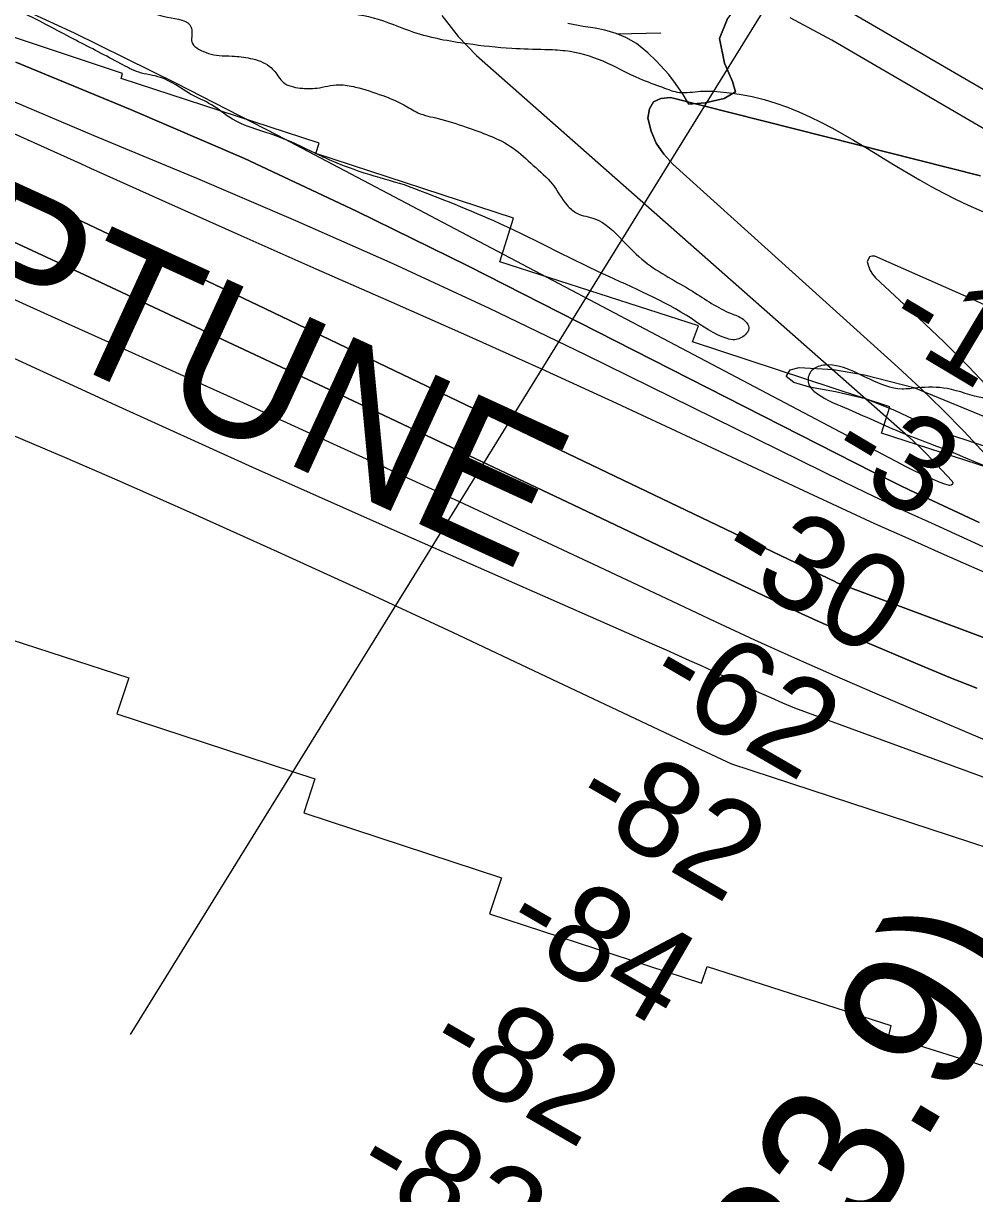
# Model space of a CAD drawing. Extents: x 3855477 to 3893699, y 299188 to 325115.
# Drawn here: x 3860894 to 3861561, y 316616 to 317436 of the extents above; entities that cross this region are included whole.
import ezdxf

# ---------------------------------------------------------------- set-up
doc = ezdxf.new("R2010")
doc.units = 0
for name, color, linetype in [('V-CHAN-NAID', 7, 'Continuous'), ('V-RIVR-EDGE', 7, 'Continuous'), ('V-RIVR-RANG', 7, 'Continuous'), ('V-RRAP-RVMT', 7, 'Continuous'), ('V-RRAP-RVMT-IDEN', 7, 'Continuous'), ('V-TOPO-DPTH', 7, 'Continuous'), ('V-TOPO-MAJR', 7, 'Continuous'), ('V-TOPO-MINR', 7, 'Continuous'), ('V-TOPO-SHOR', 7, 'Continuous'), ('V-TOPO-WATR', 7, 'Continuous'), ('V-WETL-SWMP', 7, 'Continuous')]:
    doc.layers.add(name, color=color, linetype=linetype)

msp = doc.modelspace()

# ---------------------------------------------------------------- linework, layer by layer
at = {"layer": 'V-RIVR-EDGE'}
for points in [[(3859519.27, 318133.34), (3859529.08, 318128.12), (3859557.75, 318117.29), (3859589.18, 318096.89), (3859608.3, 318091.66), (3859632.6, 318087.21), (3859655.71, 318083.17), (3859677.62, 318079.13), (3859695.14, 318076.3), (3859736.57, 318066.23), (3859764.45, 318061.38), (3859790.33, 318051.75), (3859824.18, 318038.52), (3859868.37, 318020.07), (3859890.67, 318012.05), (3859919.33, 318000.82), (3859946.39, 317985.21), (3859972.27, 317972.39), (3859987.4, 317965.98), (3859998.95, 317963.16), (3860007.3, 317958.36), (3860026.81, 317947.55), (3860045.91, 317937.54), (3860071.38, 317923.92), (3860094.87, 317913.9), (3860108.41, 317909.49), (3860130.3, 317897.08), (3860149.8, 317885.47), (3860170.5, 317876.25), (3860195.19, 317867.82), (3860221.06, 317854.21), (3860250.51, 317837.4), (3860275.18, 317822.59), (3860303.05, 317809.37), (3860359.56, 317779.34), (3860406.54, 317758.5), (3860436.79, 317744.08), (3860477.8, 317728.83), (3860496.52, 317723.61), (3860519.21, 317713.19), (3860555.84, 317695.96), (3860594.84, 317675.54), (3860632.26, 317656.32), (3860676.44, 317633.09), (3860726.58, 317605.47), (3860767.97, 317581.06), (3860790.66, 317570.64), (3860877.81, 317518.61), (3860907.67, 317504.59), (3860923.6, 317499.77), (3860947.49, 317491.74), (3860980.94, 317479.3), (3861011.2, 317471.26), (3861035.1, 317464.42), (3861065.37, 317455.98), (3861094.05, 317449.13), (3861112.77, 317445.1), (3861139.06, 317440.25), (3861167.33, 317430.22), (3861205.17, 317422.16), (3861236.25, 317418.89), (3861259.36, 317418.04), (3861273.71, 317417.2), (3861299.99, 317409.96), (3861325.86, 317397.55), (3861341.79, 317391.53), (3861353.74, 317387.91), (3861368.49, 317388.67), (3861377.65, 317388.65), (3861664.73, 317282.73), (3861681.06, 317276.71), (3861681.05, 317274.32), (3861687.02, 317270.72), (3861700.16, 317265.1), (3861705.72, 317256.72), (3861715.66, 317246.33), (3861721.22, 317241.54), (3861723.2, 317234.36), (3861726.37, 317227.58), (3861750.63, 317207.99), (3861757.38, 317197.61), (3861762.54, 317188.83), (3861767.32, 317187.22), (3861780.07, 317185.6), (3861788.02, 317178.01), (3861803.13, 317165.22), (3861810.27, 317151.65), (3861809.85, 317139.69), (3861814.21, 317132.91), (3861819.77, 317124.13), (3861817.34, 317108.59), (3861814.52, 317094.25), (3861799.35, 317086.71), (3861786.59, 317080.77), (3861777.01, 317076.81), (3861766.22, 317064.08), (3861761.83, 317062.89), (3861758.65, 317067.29), (3861753.91, 317083.24), (3861749.94, 317087.23), (3861742.77, 317089.64), (3861728.42, 317090.08), (3861720.06, 317091.29), (3861710.51, 317097.3), (3861701.37, 317107.68), (3861698.2, 317118.05), (3861695.03, 317124.04), (3861685.48, 317130.44), (3861670.34, 317131.27), (3861652.81, 317132.51), (3861648.43, 317134.11), (3861621.76, 317148.93), (3861610.22, 317154.53), (3861601.85, 317155.35), (3861592.29, 317158.16), (3861585.13, 317163.76), (3861576.78, 317170.96), (3861567.22, 317173.37), (3861541.33, 317180.21), (3861520.61, 317180.66), (3861509.85, 317179.89), (3861487.15, 317186.72), (3861457.28, 317196.76), (3861452.1, 317195.97), (3861445.31, 317191.21), (3861444.5, 317182.84), (3861448.07, 317178.45), (3861469.56, 317166.84), (3861510.97, 317148.8), (3861530.48, 317141.18), (3861552.77, 317132.36), (3861596.96, 317112.72)], [(3861161.09, 317323.03), (3861105.34, 317341.9), (3861095.39, 317346.7), (3861067.12, 317358.73), (3861040.44, 317369.16), (3861025.72, 317379.16), (3861011, 317386.77), (3860989.9, 317398.38), (3860974.77, 317402), (3860962.03, 317408.01), (3860930.58, 317424.43), (3860862.12, 317458.07), (3860828.68, 317471.31), (3860810.36, 317480.12), (3860790.46, 317487.34), (3860766.97, 317499.76), (3860758.62, 317504.56), (3860752.25, 317510.16), (3860744.29, 317512.57), (3860727.96, 317516.19), (3860714.02, 317522.6), (3860687.35, 317534.23), (3860666.25, 317542.25), (3860648.74, 317551.46), (3860633.21, 317559.47), (3860610.51, 317563.91), (3860578.66, 317578.73), (3860544.85, 317603.13), (3860519.78, 317618.33), (3860492.31, 317632.35), (3860481.57, 317638.75), (3860472.42, 317647.15), (3860466.06, 317652.34), (3860459.29, 317656.74), (3860442.18, 317667.15), (3860421.09, 317679.16), (3860388.85, 317695.18), (3860368.15, 317703.6), (3860300.85, 317726.08), (3860260.24, 317741.33), (3860222.81, 317756.17), (3860187.38, 317771.8), (3860146.39, 317795.01), (3860128.08, 317804.22), (3860109.37, 317812.24), (3860044.46, 317834.72), (3859988.33, 317859.57), (3859925.43, 317886.82), (3859887.6, 317901.26), (3859853.75, 317911.71), (3859831.85, 317919.73), (3859802.79, 317932.96), (3859772.93, 317945.78), (3859734.71, 317960.23), (3859695.31, 317982.64), (3859660.3, 318005.45), (3859631.23, 318017.47), (3859592.21, 318031.92), (3859552, 318047.96), (3859520.42, 318061.02)], [(3859768.39, 318041.05), (3859805.82, 318029), (3859833.68, 318015.78), (3859870.71, 318001.74), (3859904.56, 317989.3), (3859933.62, 317976.07), (3859963.48, 317964.04), (3859984.98, 317954.03), (3860008.45, 317939.62), (3860049.45, 317917.2), (3860076.91, 317902.79), (3860098.01, 317895.16), (3860117.92, 317885.15), (3860137.81, 317872.35), (3860159.31, 317862.33), (3860181.6, 317854.31), (3860199.92, 317845.89), (3860220.61, 317833.09), (3860254.84, 317816.26), (3860275.54, 317805.45), (3860323.69, 317776.64), (3860351.16, 317763.42), (3860381.01, 317748.6), (3860409.28, 317737.77), (3860435.16, 317727.74), (3860478.16, 317711.3), (3860508.02, 317698.07), (3860533.49, 317684.46), (3860610.33, 317651.59), (3860643.76, 317633.17), (3860673.2, 317613.57), (3860699.46, 317595.17), (3860724.93, 317580.37), (3860751.2, 317565.95), (3860789.01, 317546.33), (3860819.26, 317530.71), (3860850.69, 317509.91), (3860873.37, 317496.31), (3860894.85, 317480.31), (3860901.61, 317471.53), (3860901.6, 317468.74), (3860907.58, 317469.12), (3860918.73, 317465.11), (3860923.51, 317464.7), (3860931.48, 317464.68), (3860947.81, 317458.66), (3860971.69, 317449.04), (3860994.79, 317440.61), (3861011.51, 317433.39), (3861011.9, 317431.8), (3861012.28, 317422.23), (3861016.65, 317418.24), (3861030.99, 317413.82), (3861040.15, 317413.4), (3861052.9, 317411.77), (3861066.44, 317406.16), (3861070.02, 317402.56), (3861075.98, 317394.98), (3861087.92, 317390.96), (3861099.48, 317390.93), (3861115.03, 317393.28), (3861126.58, 317391.66), (3861145.7, 317385.64), (3861160.43, 317379.22), (3861170.38, 317373.62), (3861184.71, 317369.6), (3861204.23, 317363.57), (3861220.55, 317357.55), (3861237.27, 317348.75), (3861251.19, 317336.75), (3861264.71, 317323.57), (3861275.03, 317308.8), (3861281.79, 317303.2), (3861294.54, 317299.19), (3861313.63, 317284.39), (3861329.53, 317269.21), (3861362.96, 317248.4), (3861390.02, 317232.79), (3861398.38, 317228.79), (3861402.35, 317222.4), (3861399.95, 317218.02), (3861392.37, 317214.45), (3861387.19, 317215.26), (3861362.11, 317229.27), (3861300.42, 317260.51), (3861223.59, 317297.77), (3861161.09, 317323.03)]]:
    msp.add_spline(points, degree=3, dxfattribs=at)
at = {"layer": 'V-RIVR-RANG'}
msp.add_line((3861452.44, 317509.83), (3860968.71, 316727.27), dxfattribs=at)
at = {"layer": 'V-RRAP-RVMT'}
for p, q in [((3860963.34, 317401.24), (3860825.71, 317446.87)), ((3860962.47, 317397.72), (3860963.34, 317401.24)), ((3861101.15, 317352.27), (3860962.47, 317397.72)), ((3861098.76, 317344.95), (3861101.15, 317352.27)), ((3861237.36, 317299.59), (3861098.76, 317344.95)), ((3861227.79, 317269.16), (3861237.36, 317299.59)), ((3861367.01, 317224.23), (3861227.79, 317269.16)), ((3861362.99, 317212.89), (3861367.01, 317224.23)), ((3861501.32, 317167.46), (3861362.99, 317212.89)), ((3861495.36, 317148.95), (3861501.32, 317167.46)), ((3861634.22, 317103.97), (3861495.36, 317148.95)), ((3860829.08, 317022.25), (3860967.72, 316977.28)), ((3860967.72, 316977.28), (3860959.43, 316952.07)), ((3860959.43, 316952.07), (3861098.19, 316906.58)), ((3861098.19, 316906.58), (3861090.32, 316882.6)), ((3861090.32, 316882.6), (3861229.1, 316837.15)), ((3861229.1, 316837.15), (3861220.68, 316811.95)), ((3861220.68, 316811.95), (3861369.22, 316763.13)), ((3861369.22, 316763.13), (3861373.12, 316775)), ((3861373.12, 316775), (3861501.87, 316733.51)), ((3861501.87, 316733.51), (3861500.2, 316726.35)), ((3861500.2, 316726.35), (3861638.27, 316682.77))]:
    msp.add_line(p, q, dxfattribs=at)
at = {"layer": 'V-TOPO-DPTH'}
for points in [[(3861601.29, 317369.72), (3861302.2, 317544.09)], [(3860888.52, 317409.07), (3860968.96, 317376.02), (3861048.71, 317341.45), (3861127.44, 317304.62), (3861205.49, 317266.28), (3861490.14, 317121.36), (3861498.63, 317117.1), (3861507.14, 317112.89), (3861515.71, 317108.77), (3861524.3, 317104.72), (3861563.79, 317086.31)], [(3860888.52, 317409.07), (3860968.96, 317376.02), (3861048.71, 317341.45), (3861127.44, 317304.62), (3861205.49, 317266.28), (3861490.14, 317121.36), (3861498.63, 317117.1), (3861507.14, 317112.89), (3861515.71, 317108.77), (3861524.3, 317104.72), (3861563.79, 317086.31)], [(3861568.15, 317134.3), (3861553.32, 317150.07), (3861538.21, 317165.55), (3861522.65, 317180.57), (3861506.79, 317195.31), (3861349.03, 317337.68), (3861342.74, 317344.68), (3861337.54, 317352.29), (3861334.01, 317360.79), (3861331.59, 317369.89), (3861332.83, 317376.47), (3861335.61, 317381.36), (3861340.73, 317383.69), (3861347.4, 317384.32), (3861564.88, 317329.31)], [(3861568.15, 317134.3), (3861553.32, 317150.07), (3861538.21, 317165.55), (3861522.65, 317180.57), (3861506.79, 317195.31), (3861349.03, 317337.68), (3861342.74, 317344.68), (3861337.54, 317352.29), (3861334.01, 317360.79), (3861331.59, 317369.89), (3861332.83, 317376.47), (3861335.61, 317381.36), (3861340.73, 317383.69), (3861347.4, 317384.32), (3861564.88, 317329.31)], [(3862398.61, 316693.2), (3862222.96, 316784.06), (3862199.72, 316796.23), (3862176.56, 316808.56), (3862153.53, 316821.11), (3861655.23, 317013.53), (3861624.19, 317026.54), (3861537.43, 317064.64), (3861514.09, 317075), (3861490.8, 317085.47), (3861467.59, 317096.11), (3861444.43, 317106.87), (3861362.07, 317145.5), (3861309.75, 317169.79), (3861257.31, 317193.81), (3861204.69, 317217.42), (3861151.94, 317240.76), (3861099.14, 317263.99), (3861046.39, 317287.34), (3860993.73, 317310.87), (3860941.12, 317334.53), (3860934.1, 317337.7), (3860878.1, 317363.14)], [(3862398.61, 316693.2), (3862222.96, 316784.06), (3862199.72, 316796.23), (3862176.56, 316808.56), (3862153.53, 316821.11), (3861655.23, 317013.53), (3861624.19, 317026.54), (3861537.43, 317064.64), (3861514.09, 317075), (3861490.8, 317085.47), (3861467.59, 317096.11), (3861444.43, 317106.87), (3861362.07, 317145.5), (3861309.75, 317169.79), (3861257.31, 317193.81), (3861204.69, 317217.42), (3861151.94, 317240.76), (3861099.14, 317263.99), (3861046.39, 317287.34), (3860993.73, 317310.87), (3860941.12, 317334.53), (3860934.1, 317337.7), (3860878.1, 317363.14)], [(3860763.55, 317340.49), (3860936.61, 317259.94), (3861022.39, 317219.87), (3861108.1, 317179.65), (3861193.7, 317139.2), (3861279.24, 317098.6), (3861422.9, 317030.17), (3861436.58, 317023.75), (3861450.31, 317017.44), (3861464.12, 317011.3), (3861477.98, 317005.27), (3861525.34, 316984.99), (3861543.74, 316977.42), (3861562.28, 316970.2)], [(3861562.28, 316970.2), (3861543.74, 316977.42), (3861525.34, 316984.99), (3861477.98, 317005.27), (3861464.12, 317011.3), (3861450.31, 317017.44), (3861436.58, 317023.75), (3861422.9, 317030.17), (3861279.24, 317098.6), (3861193.7, 317139.2), (3861108.1, 317179.65), (3861022.39, 317219.87), (3860936.61, 317259.94), (3860763.55, 317340.49)], [(3860871.22, 317327.44), (3860967.49, 317281.91), (3861063.64, 317236.13), (3861159.7, 317190.18), (3861463.07, 317044.58), (3861463.36, 317044.44), (3861463.65, 317044.3), (3861464.82, 317043.76), (3861466.28, 317043.19), (3861624.34, 316984.23)], [(3861624.34, 316984.23), (3861466.28, 317043.19), (3861464.82, 317043.76), (3861463.65, 317044.3), (3861463.36, 317044.44), (3861463.07, 317044.58), (3861159.7, 317190.18), (3861063.64, 317236.13), (3860967.49, 317281.91), (3860871.22, 317327.44)]]:
    msp.add_lwpolyline(points, dxfattribs=at)
at = {"layer": 'V-TOPO-MAJR'}
msp.add_lwpolyline([(3861591.76, 316923.6), (3861490.7, 316966.53), (3861462.58, 316978.68), (3861434.56, 316991.05), (3861406.69, 317003.76), (3861378.92, 317016.7), (3861340.58, 317034.84), (3861293.67, 317056.94), (3861246.71, 317078.91), (3861199.67, 317100.71), (3861152.58, 317122.39), (3861147.6, 317124.67), (3861097.95, 317147.35), (3861048.26, 317169.97), (3860998.53, 317192.47), (3860948.77, 317214.91), (3860923.29, 317226.36), (3860860.77, 317254.51)], dxfattribs=at)
at = {"layer": 'V-TOPO-MINR'}
for points in [[(3861187.26, 317441.76), (3861198.54, 317427.18), (3861211.5, 317413.69), (3861514.01, 317146.8), (3861518.32, 317142.88), (3861522.56, 317138.89), (3861526.68, 317134.77), (3861530.72, 317130.58), (3861544.96, 317115.39), (3861545.33, 317114.08), (3861545.2, 317113.06), (3861544.36, 317112.49), (3861543.02, 317112.2), (3861539.71, 317113.23), (3861536.43, 317114.36), (3861533.22, 317115.66), (3861530.05, 317117.07), (3861518.82, 317122.4), (3861516.49, 317123.52), (3861514.16, 317124.67), (3861511.86, 317125.84), (3861509.56, 317127.03), (3861072.13, 317357.7), (3861001.1, 317394.1), (3860929.53, 317429.36), (3860857.16, 317462.93)], [(3861609.61, 317337.54), (3861460.52, 317424.46), (3861431.49, 317440.19)], [(3861563.79, 317086.31), (3861524.3, 317104.72), (3861515.71, 317108.77), (3861507.14, 317112.89), (3861498.63, 317117.1), (3861490.14, 317121.36), (3861205.49, 317266.28), (3861127.44, 317304.62), (3861048.71, 317341.45), (3860968.96, 317376.02), (3860888.52, 317409.07)], [(3861597.4, 317055.23), (3861530.37, 317085.72), (3861514.91, 317092.84), (3861499.49, 317100.05), (3861484.14, 317107.4), (3861468.83, 317114.85), (3861287.95, 317203.92), (3861220.69, 317236.25), (3861153.04, 317267.73), (3861084.81, 317297.92), (3861016.19, 317327.26), (3860943.51, 317357.54), (3860910.98, 317371.19), (3860878.51, 317384.97)], [(3861564.88, 317329.31), (3861347.4, 317384.32), (3861340.73, 317383.69), (3861335.61, 317381.36), (3861332.83, 317376.47), (3861331.59, 317369.89), (3861334.01, 317360.79), (3861337.54, 317352.29), (3861342.74, 317344.68), (3861349.03, 317337.68), (3861506.79, 317195.31), (3861522.65, 317180.57), (3861538.21, 317165.55), (3861553.32, 317150.07), (3861568.15, 317134.3)], [(3862398.61, 316693.2), (3862222.96, 316784.06), (3862199.72, 316796.23), (3862176.56, 316808.56), (3862153.53, 316821.11), (3861655.23, 317013.53), (3861624.19, 317026.54), (3861537.43, 317064.64), (3861514.09, 317075), (3861490.8, 317085.47), (3861467.59, 317096.11), (3861444.43, 317106.87), (3861362.07, 317145.5), (3861309.75, 317169.79), (3861257.31, 317193.81), (3861204.69, 317217.42), (3861151.94, 317240.76), (3861099.14, 317263.99), (3861046.39, 317287.34), (3860993.73, 317310.87), (3860941.12, 317334.53), (3860934.1, 317337.7), (3860878.1, 317363.14)], [(3861562.28, 316970.2), (3861543.74, 316977.42), (3861525.34, 316984.99), (3861477.98, 317005.27), (3861464.12, 317011.3), (3861450.31, 317017.44), (3861436.58, 317023.75), (3861422.9, 317030.17), (3861279.24, 317098.6), (3861193.7, 317139.2), (3861108.1, 317179.65), (3861022.39, 317219.87), (3860936.61, 317259.94), (3860763.55, 317340.49)], [(3861624.34, 316984.23), (3861466.28, 317043.19), (3861464.82, 317043.76), (3861463.65, 317044.3), (3861463.36, 317044.44), (3861463.07, 317044.58), (3861159.7, 317190.18), (3861063.64, 317236.13), (3860967.49, 317281.91), (3860871.22, 317327.44)], [(3861568.95, 317238.17), (3861558.99, 317242.94), (3861490.64, 317272.97), (3861488.54, 317273.05), (3861486.9, 317272.53), (3861485.44, 317269.05), (3861486.2, 317265.93), (3861487.35, 317263), (3861489.07, 317260.37), (3861491.19, 317257.94), (3861521.69, 317229.6), (3861539.12, 317212.91), (3861556.21, 317195.89), (3861572.78, 317178.37)], [(3861947.61, 316768.2), (3861434.58, 316956.09), (3861426.31, 316959.63), (3861418.07, 316963.24), (3861409.87, 316966.95), (3861401.7, 316970.73), (3861401.56, 316970.79), (3861393.47, 316974.57), (3861385.37, 316978.32), (3861377.25, 316982.03), (3861369.13, 316985.72), (3861360.98, 316989.38), (3861352.84, 316993.03), (3861344.68, 316996.65), (3861336.52, 317000.26), (3861154.01, 317080.71), (3861054.78, 317124.92), (3860955.77, 317169.66), (3860857.13, 317215.19)], [(3862585.42, 316454.74), (3862103.1, 316682.52), (3862102.24, 316682.93), (3862100.5, 316683.73), (3862096.31, 316685.59), (3862093.92, 316686.57), (3862091.47, 316687.41), (3862088.98, 316688.12), (3862086.46, 316688.68), (3861390.39, 316916.73), (3861368.99, 316926.77), (3861347.62, 316936.86), (3861256.15, 316980.28), (3861194.89, 317009.08), (3861133.49, 317037.6), (3861071.9, 317065.67), (3861010.16, 317093.45), (3860959.67, 317115.96), (3860922.94, 317131.92), (3860886.02, 317147.42)]]:
    msp.add_lwpolyline(points, dxfattribs=at)
at = {"layer": 'V-TOPO-SHOR'}
msp.add_lwpolyline([(3861360.24, 317379.56), (3861371.86, 317380.49), (3861385.1, 317383.52), (3861393.07, 317388.2), (3861391.03, 317395.61), (3861385.35, 317408.34), (3861381.84, 317425.8), (3861387.25, 317438.95), (3861400.11, 317456.77), (3861420.37, 317475.57), (3861442.19, 317492.24), (3861456.58, 317505.29), (3861463.6, 317519.48), (3861465.36, 317537.42), (3861459.33, 317567.05), (3861445, 317610.5), (3861431.49, 317632.29), (3861412.69, 317652.55), (3861385.99, 317674.47), (3861347.19, 317701.28), (3861321.42, 317711.58), (3861292.5, 317723.49), (3861257.96, 317734.62)], dxfattribs=at)
at = {"layer": 'V-TOPO-WATR'}
msp.add_lwpolyline([(3861601.29, 317369.72), (3861302.2, 317544.09)], dxfattribs=at)
at = {"layer": 'V-WETL-SWMP'}
for p, q in [((3861286.14, 317434.06), (3861275.61, 317436.28)), ((3861387.25, 317438.95), (3861381.84, 317425.8)), ((3861294.57, 317433.02), (3861286.14, 317434.06)), ((3861301.47, 317431.6), (3861294.57, 317433.02)), ((3861309.5, 317429.21), (3861301.47, 317431.6)), ((3861316.19, 317426.46), (3861309.5, 317429.21)), ((3861309.84, 317429.08), (3861340.79, 317429.58)), ((3861323.63, 317422.16), (3861316.19, 317426.46)), ((3861331.63, 317415.55), (3861323.63, 317422.16)), ((3861381.84, 317425.8), (3861385.35, 317408.34)), ((3861337.33, 317409.93), (3861331.63, 317415.55)), ((3861346.25, 317400.43), (3861337.33, 317409.93)), ((3861385.35, 317408.34), (3861391.03, 317395.61)), ((3861350.98, 317394.05), (3861346.25, 317400.43)), ((3861356.28, 317386.51), (3861350.98, 317394.05)), ((3861391.03, 317395.61), (3861393.06, 317388.2)), ((3861360.24, 317379.56), (3861356.28, 317386.51)), ((3861393.06, 317388.2), (3861385.1, 317383.52)), ((3861371.86, 317380.49), (3861360.24, 317379.56)), ((3861385.1, 317383.52), (3861371.86, 317380.49))]:
    msp.add_line(p, q, dxfattribs=at)
msp.add_lwpolyline([(3861589, 317132.91), (3861543.93, 317147.57), (3861521.94, 317156.73), (3861504.68, 317164.8), (3861484.25, 317172.9), (3861463.27, 317177.85), (3861444.91, 317181.19), (3861433.9, 317184.46), (3861428.68, 317188.72), (3861431.36, 317193.42), (3861437.69, 317194.93), (3861461.86, 317193.63), (3861483.38, 317189.73), (3861517.99, 317180.96), (3861556.21, 317165.32), (3861602.28, 317146.44)], dxfattribs=at)

# ---------------------------------------------------------------- texts
at = {"layer": 'V-CHAN-NAID'}
msp.add_text('NEPTUNE "24" (23.9)', height=100, rotation=59.12669, dxfattribs=at).set_placement((3860933.2, 315661.1))
at = {"layer": 'V-RIVR-RANG'}
for s, rotation, p in [('-18', 329.09833, (3861494.83, 317219.71)), ('-3', 329.09833, (3861454.55, 317127.28)), ('-30', 329.09833, (3861377.37, 317056.93)), ('-62', 329.91339, (3861327.64, 316968.82)), ('-82', 329.91339, (3861275.58, 316883.42)), ('-84', 329.91339, (3861226.94, 316796.03)), ('-82', 329.91339, (3861173.28, 316711.55)), ('-82', 329.91339, (3861122.14, 316625.62))]:
    msp.add_text(s, height=67, rotation=rotation, dxfattribs=at).set_placement(p)
at = {"layer": 'V-RRAP-RVMT-IDEN'}
msp.add_text('NEPTUNE', height=100, rotation=335.36659, dxfattribs=at).set_placement((3860661.52, 317318.98))

doc.saveas('drawing.dxf')
